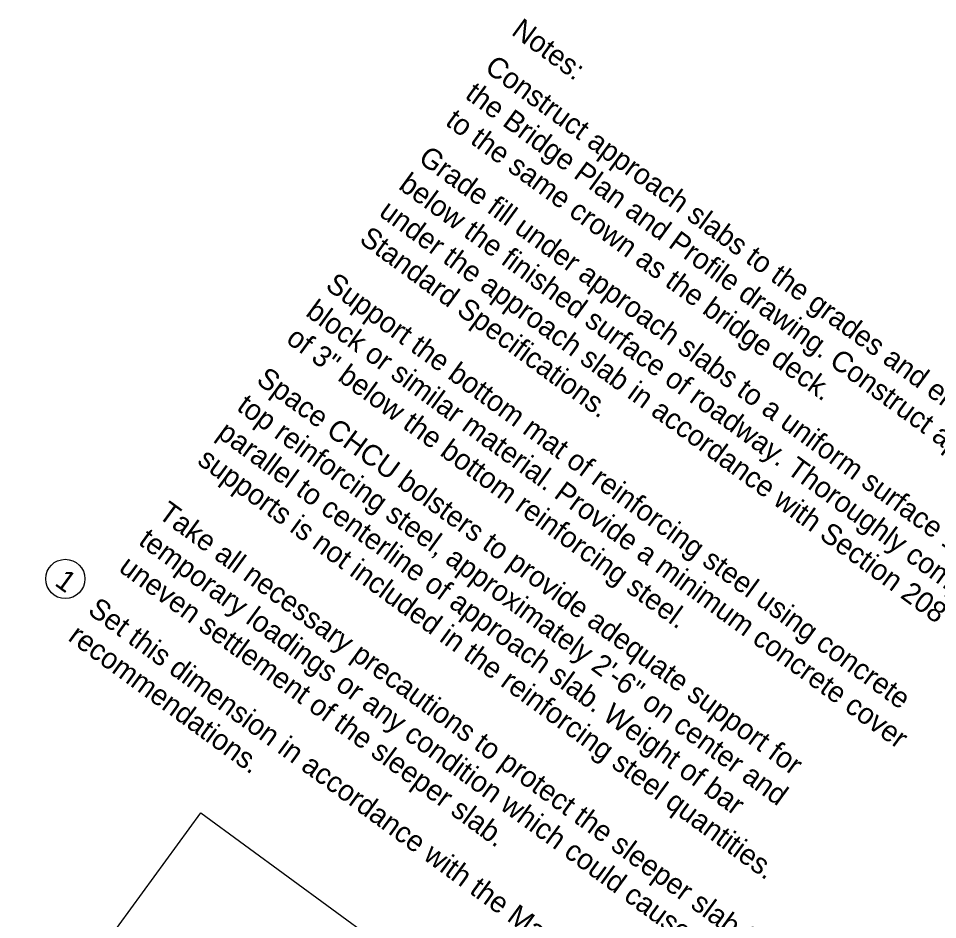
# Model space of a CAD drawing. Extents: x 1970731 to 1970899, y 796145 to 796301.
# Drawn here: x 1970837.61 to 1970859.71, y 796175.27 to 796196.93 of the extents above; entities that cross this region are included whole.
import ezdxf

# ---------------------------------------------------------------- set-up
doc = ezdxf.new("R2010")
doc.units = 0
for name, color, linetype in [('BR_AUTO DIMENSION', 7, 'Continuous'), ('BR_BORDER LINES', 7, 'Continuous'), ('BR_TEXT', 7, 'Continuous')]:
    doc.layers.add(name, color=color, linetype=linetype)

msp = doc.modelspace()

# ---------------------------------------------------------------- linework, layer by layer
at = {"layer": 'BR_AUTO DIMENSION'}
msp.add_circle((1970838.741, 796183.459), 0.472, dxfattribs=at)
at = {"layer": 'BR_BORDER LINES'}
for p, q in [((1970829.532, 796160.81), (1970842, 796177.84)), ((1970842, 796177.84), (1970859.483, 796165.04))]:
    msp.add_line(p, q, dxfattribs=at)

# ---------------------------------------------------------------- texts
at = {"layer": 'BR_TEXT'}
for s, height, p in [('Notes:', 0.4999, (1970849.437, 796196.555)), ('Construct approach slabs to the grades and elevations shown on', 0.49995, (1970848.793, 796195.676)), ('the Bridge Plan and Profile drawing. Construct approach slabs', 0.49995, (1970848.321, 796195.03)), ('to the same crown as the bridge deck.', 0.49995, (1970847.848, 796194.385)), ('Grade fill under approach slabs to a uniform surface 1\'-0"', 0.49995, (1970847.198, 796193.497)), ('below the finished surface of roadway. Thoroughly compact fill', 0.49995, (1970846.725, 796192.851)), ('under the approach slab in accordance with Section 208 of the', 0.49995, (1970846.253, 796192.206)), ('Standard Specifications.', 0.49995, (1970845.78, 796191.561)), ('Support the bottom mat of reinforcing steel using concrete', 0.49995, (1970844.966, 796190.448)), ('block or similar material. Provide a minimum concrete cover', 0.49995, (1970844.493, 796189.803)), ('of 3" below the bottom reinforcing steel.', 0.49995, (1970844.021, 796189.157)), ('Space CHCU bolsters to provide adequate support for', 0.49995, (1970843.305, 796188.18)), ('top reinforcing steel, approximately 2\'-6" on center and', 0.49995, (1970842.833, 796187.534)), ('parallel to centerline of approach slab. Weight of bar', 0.49995, (1970842.36, 796186.889)), ('supports is not included in the reinforcing steel quantities.', 0.49995, (1970841.888, 796186.244)), ('Take all necessary precautions to protect the sleeper slab from', 0.49995, (1970840.943, 796184.954)), ('temporary loadings or any condition which could cause movements or', 0.49995, (1970840.471, 796184.309)), ('uneven settlement of the sleeper slab.  ', 0.49995, (1970839.998, 796183.663)), ('1', 0.5, (1970838.462, 796183.324)), ("Set this dimension in accordance with the Manufacturer's", 0.49995, (1970839.254, 796182.646)), ('recommendations.', 0.49995, (1970838.781, 796182.001))]:
    msp.add_text(s, height=height, rotation=323.7906, dxfattribs=at).set_placement(p)

doc.saveas('drawing.dxf')
